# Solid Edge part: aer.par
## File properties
Username: Kasutaja
Author: Kasutaja
Template: Iso Metric Part.par
Last saved by: Kasutaja
Revision: 6
Application: Solid Edge
Accuracy: 0,990
Face Style: Model Default
Fill Style: Normal
Coef. of Thermal Exp: 0.0
Thermal Conductivity: 0.0
Specific Heat: 0.0
Modulus of Elasticity: 0.0
Poisson's Ratio: 0.0
Yield Stress: 0.0
Ultimate Stress: 0.0
Elongation: 0.0
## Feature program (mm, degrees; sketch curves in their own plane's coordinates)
lofted protrusion "unnamed LoftedProtrusion 1"
fillet "Round_4" radius 2
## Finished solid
Body 1: solid body, 8 faces, 12 edges, 6 vertices.
  Faces by surface: blend 3, spline 3, plane 2
  Edges by curve: curve on surface 6, intersection 6
Bounding box of the edges (mm; curved faces can reach further): 9.363 x 230.812 x 18.909, from (-4.6814, -230.8122, -9.4545) to (4.6813, 0, 9.4545).
Planar faces by outward normal: +y 1, -y 1
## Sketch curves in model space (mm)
ellipse centre (0, -230.8122, 0) radii 10, 4
ellipse centre (0, -156.9971, 0) radii 10, 4
ellipse centre (0, -220.8122, 0) radii 9.2445, 4
ellipse centre (0, -186.8072, 0) radii 10, 4
circle centre (0, -100, 0) radius 4
circle centre (0, 0, 0) radius 2.5
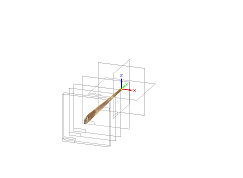
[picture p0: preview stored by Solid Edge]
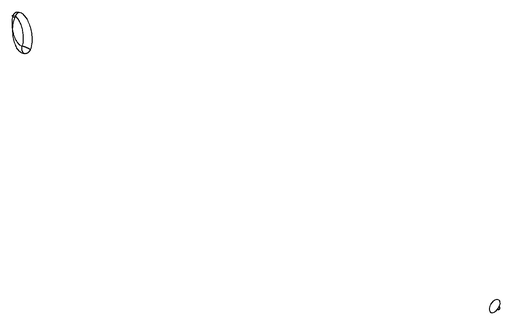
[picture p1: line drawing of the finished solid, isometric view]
